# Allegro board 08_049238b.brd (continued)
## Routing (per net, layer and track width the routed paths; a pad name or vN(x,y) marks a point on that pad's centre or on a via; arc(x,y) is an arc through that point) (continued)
APLANE: length 1936.4
  TOP w0.203: U4.11 90.81,84.74 ; U4.23 89.29,89.65 v1(89.15,89.79)
  TOP w0.254: 5.01,94.99 P2.BG4 5.01,97.1 ; C31.2 86.23,94.11 ; 51.18,89.53 C13.2 49.4,89.53 ; 85.72,99.21 J3.5 ; J3.5 84.23,100.71 ; J3.5 87.22,100.71 ; J3.5 85.72,102.21 ; 101.6,142.46 P6.1 ; P6.1 99.91,144.14 ; P6.1 101.6,145.83 ; P6.1 103.29,144.14 ; 51.18,163.07 C5.2 49.4,163.07 ; TP10.1 81.06,156.97 ; TP10.1 77.94,156.97 ; TP10.1 79.5,155.41 ; TP10.1 79.5,158.53 ; J1.3 72.77,114.66 ; J1.3 72.77,111.66 ; J1.3 74.27,113.16 ; J1.3 71.27,113.16 ; 53.21,80.9 54.1,80.9 54.1,79.97 ; 45.97,88.14 C20.2 ; 5.01,89.99 P2.BG2 5.01,92.1 ; TP12.1 38.35,158.66 ; TP12.1 38.35,155.54 ; TP12.1 39.92,157.1 ; TP12.1 36.79,157.1 ; 31.37,163.19 C42.2 29.59,163.19 ; 54.23,15.98 XC1.2 55.26,17.06 ; 92.52,127.72 C113.2 ; 5.01,73.56 P1.BG5 5.01,71.45 ; P2.DG9 9.51,109.6 ; P2.DG9 9.51,107.49 ; P2.DG9 10.56,108.54 ; 29.38,8.44 XP2.PAD2 ; XP2.PAD2 30.87,6.71 ; XP2.PAD2 32.36,8.44 ; 89.31,100.71 J3.4 ; J3.4 90.81,102.21 ; J3.4 92.3,100.71 ; J3.4 90.81,99.21 ; v1(93.47,85.72) 93.21,85.99 U4.14 ; P1.DG9 10.56,82.51 ; P1.DG9 9.51,81.45 ; P1.DG9 9.51,83.56 ; P2.DG4 10.56,96.04 ; P2.DG4 9.51,97.1 ; P2.DG4 9.51,94.99 ; 5.01,61.45 P1.BG1 5.01,63.56 ; 5.01,102.1 P2.BG6 5.01,99.99 ; 5.01,99.6 P2.BG5 5.01,97.49 ; 101.15,84.65 J6.3 ; 70.51,132.44 S2.4 ; S2.4 72.75,132.44 ; S2.4 71.63,131.19 ; J2.5 36.3,70.99 ; J2.5 34.8,72.49 ; J2.5 34.8,69.49 ; J2.5 33.3,70.99 ; 79.12,58.83 J4.5 ; J4.5 80.62,60.33 ; J4.5 77.62,60.33 ; J4.5 79.12,61.82 ; 51.02,15.32 XC4.N 53.18,15.32 ; 106.02,135.38 C1.N 103.02,135.38 ; P1.DG5 10.56,72.51 ; P1.DG5 9.51,71.45 ; P1.DG5 9.51,73.56 ; 9.51,104.99 P2.DG8 ; P2.DG8 10.56,106.04 ; P2.DG8 9.51,107.1 ; C24.2 94.87,93.35 ; TP4.1 20.74,157.23 ; TP4.1 19.18,155.66 ; TP4.1 19.18,158.79 ; TP4.1 17.61,157.23 ; 14.73,139.86 C110.N ; 32.73,95.73 DS2.C 32.73,94 ; 5.01,68.95 P1.BG4 5.01,71.06 ; 86.3,142.46 P6.2 ; P6.2 84.61,144.14 ; P6.2 86.3,145.83 ; P6.2 87.99,144.14 ; P2.DG2 10.56,91.04 ; P2.DG2 9.51,89.99 ; P2.DG2 9.51,92.1 ; 79.12,63.91 J4.2 ; J4.2 80.62,65.41 ; J4.2 79.12,66.9 ; J4.2 77.62,65.41 ; 54.5,34.42 XU1.7 ; v1(93.34,87.88) 92.95,87.49 U4.17 ; 63.25,168.2 U6.1 64.3,169.65 ; 5.01,102.49 P2.BG7 5.01,104.6 ; TP19.1 96.52,135.55 ; TP19.1 94.96,133.99 ; TP19.1 98.08,133.99 ; 9.51,61.45 P1.DG1 ; P1.DG1 9.51,63.56 ; P1.DG1 10.56,62.51 ; 32.73,19.42 XC6.2 32.73,17.26 ; v3(87,85.85) 87.13,85.99 U4.5 ; 29.86,33.02 XU3.7 30.56,31.65 ; 44.49,169.77 U11.1 43.43,168.33 ; J1.2 69.19,113.16 ; J1.2 67.69,114.66 ; J1.2 67.69,111.66 ; J1.2 66.19,113.16 ; U4.2 87.26,87.49 v3(87.12,87.63) ; 29.72,167.58 C56.N 29.72,169.74 ; J2.2 34.8,77.57 ; J2.2 33.3,76.07 ; J2.2 36.3,76.07 ; J2.2 34.8,74.57 ; 83.19,84.96 C22.1 ; 5.01,83.95 P1.BG10 5.01,86.06 ; P2.DG3 10.56,93.54 ; P2.DG3 9.51,92.49 ; P2.DG3 9.51,94.6 ; C33.2 57.09,166.03 ; 5.01,76.45 P1.BG7 5.01,78.56 ; 9.51,109.99 P2.DG10 ; P2.DG10 9.51,112.1 ; P2.DG10 10.56,111.04 ; 30.87,1.26 XP2.PAD3 ; XP2.PAD3 30.87,4.72 ; XP2.PAD3 29.38,2.99 ; 9.51,76.45 P1.DG7 ; P1.DG7 9.51,78.56 ; P1.DG7 10.56,77.51 ; 39.88,69.49 J2.4 ; J2.4 38.38,70.99 ; J2.4 39.88,72.49 ; J2.4 41.38,70.99 ; 71.4,46.23 72.52,46.23 ; 72.52,46.23 72.52,47.47 ; 72.52,46.23 72.52,44.98 ; 5.01,92.49 P2.BG3 5.01,94.6 ; P1.DG3 9.51,68.56 ; P1.DG3 9.51,66.45 ; P1.DG3 10.56,67.51 ; P1.DG10 10.56,85.01 ; P1.DG10 9.51,86.06 ; P1.DG10 9.51,83.95 ; 9.51,97.49 P2.DG5 ; P2.DG5 10.56,98.54 ; P2.DG5 9.51,99.6 ; 71.78,59.18 S1.1 ; S1.1 74.27,59.18 ; S1.1 73.03,60.3 ; C11.2 52.45,86.36 ; 30.52,169.99 C62.2 30.52,172.15 ; P1.DG8 9.51,81.06 ; P1.DG8 10.56,80.01 ; P1.DG8 9.51,78.95 ; 60.62,57.02 R5.2 59.69,57.91 ; 5.01,112.1 P2.BG10 5.01,109.99 ; 9.51,68.95 P1.DG4 ; P1.DG4 9.51,71.06 ; P1.DG4 10.56,70.01 ; 50.8,83.19 49.02,83.19 ; P2.DG6 9.51,102.1 ; P2.DG6 9.51,99.99 ; P2.DG6 10.56,101.04 ; XC7.2 32.75,17.18 ; 32.6,100.05 DS1.C 32.6,98.32 ; 85.72,104.29 J3.2 ; J3.2 84.23,105.79 ; J3.2 87.22,105.79 ; J3.2 85.72,107.29 ; XU2.6 v1(36.32,17.53) ; J2.3 39.88,77.57 ; J2.3 41.38,76.07 ; J2.3 39.88,74.57 ; J2.3 38.38,76.07 ; P2.DG1 10.56,88.54 ; P2.DG1 9.51,87.49 ; P2.DG1 9.51,89.6 ; XY1.4 55.63,19.13 ; XY1.4 54.55,20.52 ; XY1.4 53.47,19.13 ; 50.46,172.02 C57.2 50.46,169.86 ; 101.15,89.34 J6.2 104.41,91.55 ; J4.4 84.2,61.82 ; J4.4 82.7,60.33 ; J4.4 84.2,58.83 ; J4.4 85.7,60.33 ; P1.DG2 9.51,66.06 ; P1.DG2 10.56,65.01 ; P1.DG2 9.51,63.95 ; 84.2,63.91 J4.3 ; J4.3 84.2,66.9 ; J4.3 82.7,65.41 ; J4.3 85.7,65.41 ; J1.4 72.77,109.58 ; J1.4 71.27,108.08 ; J1.4 74.27,108.08 ; J1.4 72.77,106.58 ; 5.01,89.6 P2.BG1 5.01,87.49 ; 10.67,169.86 C52.N 10.67,167.7 ; 59.69,115.54 R19.2 ; R4.2 59.69,119.48 ; P2.DG7 9.51,104.6 ; P2.DG7 10.56,103.54 ; P2.DG7 9.51,102.49 ; S1.2 65.15,60.3 ; S1.2 66.4,59.18 ; S1.2 63.91,59.18 ; 46.36,83.57 46.36,84.46 ; 46.36,83.57 47.28,83.57 ; 46.36,83.57 46.36,82.68 ; 37.28,166.15 C105.2 35.11,166.15 ; 92.27,128.65 C112.N 90.11,128.65 ; 59.69,53.95 R18.2 ; 72.52,54.1 72.52,55.35 ; 72.52,54.1 72.52,52.86 ; 72.52,54.1 71.4,54.1 ; 24.26,168.45 U7.1 25.31,169.9 ; 86.87,129.54 C115.2 86.87,127.76 ; J1.5 69.19,108.08 ; J1.5 67.69,109.58 ; J1.5 67.69,106.58 ; J1.5 66.19,108.08 ; TP2.1 59.73,156.97 ; TP2.1 58.17,155.41 ; TP2.1 58.17,158.53 ; TP2.1 56.6,156.97 ; 84.58,168.2 U10.1 85.64,169.65 ; 11.34,172.28 C58.2 11.34,170.12 ; P1.DG6 9.51,76.06 ; P1.DG6 9.51,73.95 ; P1.DG6 10.56,75.01 ; 5.01,107.49 P2.BG9 5.01,109.6 ; 91.29,83.76 U4.12 ; 49.4,94.49 C12.2 ; C12.2 50.29,95.42 ; C12.2 51.18,94.49 ; 70.99,169.61 C55.N 70.99,167.45 ; XU2.31 45.93,19.48 v1(46.23,19.18) 45.88,18.83 XU2.30 ; 5.01,68.56 P1.BG3 5.01,66.45 ; 56.22,24.73 XC2.2 ; J3.3 90.81,107.29 ; J3.3 90.81,104.29 ; J3.3 89.31,105.79 ; J3.3 92.3,105.79 ; 86.23,89.28 C40.2 ; 21.96,1.26 XP2.PAD4 ; XP2.PAD4 21.96,4.72 ; XP2.PAD4 23.45,2.99 ; 90.79,83.76 U4.11 ; 49.66,167.45 C51.N 49.66,169.61 ; 39.38,99.39 U15.4 40.02,100 v1(39.75,100.26) ; 5.01,83.56 P1.BG9 5.01,81.45 ; U4.19 91.29,89.56 v1(91.06,89.79) 90.79,89.52 U4.20 ; 52.2,83.31 52.2,84.2 ; 40.89,82.93 C21.2 40.89,81.15 ; C10.2 44.96,95.29 ; 32.73,96.16 CR3.C 32.73,97.89 ; C92.N 76.58,117.79 ; S2.3 71.63,125.81 ; S2.3 72.75,124.56 ; S2.3 70.51,124.56 ; 41.24,89.66 C7.2 ; XY1.2 56.95,24.52 ; XY1.2 55.87,23.13 ; XY1.2 56.95,21.75 ; 35.33,6.34 XP1.6 ; XP1.6 35.33,8.95 ; XP1.6 34.02,7.65 ; 72.52,163.07 C39.2 70.74,163.07 ; 72.17,169.73 C61.2 ; 5.01,78.95 P1.BG8 5.01,81.06 ; C37.2 78.42,166.03 ; 5.01,76.06 P1.BG6 5.01,73.95 ; 5.01,104.99 P2.BG8 5.01,107.1 ; 21.96,6.71 XP2.PAD1 ; XP2.PAD1 21.96,10.17 ; XP2.PAD1 23.45,8.44 ; XP2.5 28.85,8.55 ; C34.2 18.1,166.28 ; 5.01,66.06 P1.BG2 5.01,63.95 ; 12.32,163.32 C43.2 10.54,163.32 ; 94.74,88.26 C38.2 ; XC8.2 50.61,16.17
  TOP w0.279: U4.8 89.29,84.1 88.89,83.7 ; v1(91.06,83.82) 90.81,84.07 90.81,84.74
  TOP w0.381: XU3.7 v1(30.56,34.59) ; XU1.7 v1(55.2,35.81)
  TOP w0.508: v1(76.71,84.45) C99.1 ; C99.1 v1(75.18,84.45) ; C99.1 v1(75.95,85.47) ; v1(71.37,84.45) C75.1 ; C75.1 v1(72.14,85.47) ; C75.1 v1(72.77,84.45) ; XP2.PAD4 v3(20,2.99) ; U4.12 v3(91.92,84.74) ; C37.2 v1(77.34,165.23) ; C11.2 v3(51.44,85.47) ; v1(49.78,14.86) 49.53,15.11 XC8.2 ; XC3.2 v1(43.78,25.23) ; v1(104.01,83.82) 104.41,84.21 J6.3 ; XC1.2 v3(55.26,14.87) ; C56.N v1(28.32,168.66) ; C57.2 v1(49.53,170.94) ; v3(68.33,85.47) C74.1 ; C74.1 v3(67.44,84.45) ; C74.1 v3(69.22,84.45) ; v1(71.21,80.64) C64.2 ; C64.2 v1(72.14,79.63) ; C64.2 v1(73.03,80.64) ; 72.14,89.03 v1(71.37,89.03) ; 72.14,89.03 v1(72.14,88.01) ; 72.14,89.03 v1(72.9,89.03) ; C13.2 v3(50.29,88.65) ; XC6.2 v3(31.57,18.34) ; v1(67.92,80.57) 68,80.64 C65.2 ; S2.4 v3(71.63,133.71) ; C22.1 v1(82.55,85.85) ; v1(102.49,90.04) 103.12,90.04 J6.2 ; C33.2 v1(56.01,165.1) ; C30.2 v1(18.8,172.34) ; CR3.C 31.24,97.03 v1(31.37,97.16) ; C55.N v1(69.6,168.53) ; J6.2 105.03,89.69 v1(105.03,90.04) ; J6.2 104.41,89.4 v1(103.76,90.04) ; J6.2 106.93,90.04 v1(106.3,90.04) ; XC4.N v1(52.1,14.07) ; 68.33,89.03 v1(68.33,88.01) ; 68.33,89.03 v1(67.94,89.03) ; 68.33,89.03 v1(69.09,89.03) ; v1(75.95,88.01) 75.95,89.03 ; 75.95,89.03 v1(76.71,89.03) ; 75.95,89.03 v1(75.18,89.03) ; C65.2 v1(68.33,79.63) ; C65.2 v1(69.25,80.64) ; C52.N v1(9.27,168.78) ; v1(14.73,142.09) C110.N v1(16.26,140.94) ; XC5.2 47.42,14.94 v1(47.5,14.86) ; J6.3 106.93,83.82 v1(106.43,83.82) ; J6.3 103.12,83.82 v1(102.62,83.82) ; J6.3 105.28,84.12 v1(105.28,83.82) ; 72.14,92.84 v1(72.14,93.98) ; 72.14,92.84 v1(73.06,92.84) ; 72.14,92.84 v1(71.21,92.84) ; C61.2 v3(70.99,170.81) ; C49.1 v1(75.06,92.96) ; C49.1 v1(76.71,92.96) ; C49.1 v1(75.95,93.98) ; C113.2 v1(93.6,128.82) ; 72.52,46.23 v3(73.66,46.23) ; R5.2 59.69,57 v1(60.58,57) ; XC7.2 v3(31.47,16.1) ; XP2.5 v1(28.12,10.11) ; C43.2 v1(11.43,164.08) ; 52.2,84.2 51.82,83.82 v3(51.44,84.2) ; C39.2 v1(71.63,163.83) ; U7.1 v1(24.26,171.58) ; U11.1 v1(43.43,171.07) ; S1.1 v3(73.03,57.78) ; C34.2 v1(17.02,165.35) ; C42.2 v1(30.48,164.21) ; C51.N v1(48.39,168.53) ; C5.2 v1(50.29,163.83) ; v3(59.69,96.52) C147.N v3(59.69,99.19) ; 54.1,80.9 v1(54.74,80.9) ; R18.2 v3(60.81,54.84) ; XD1.C v1(51.59,25.3) ; C10.2 v1(44.2,94.36) ; XY1.2 v1(57.77,23.13) ; v1(31.5,99.19) DS1.C ; v1(76.58,115.06) C92.N v1(78.49,116.71) ; R4.2 v1(60.58,118.59) ; 68.33,92.84 v1(67.82,92.84) ; 68.33,92.84 v1(68.33,93.98) ; 68.33,92.84 v1(69.25,92.84) ; C62.2 v1(29.59,171.07) ; C101.2 v1(75.18,80.64) ; C101.2 v1(76.87,80.64) ; C101.2 v1(75.95,79.63) ; 88.89,83.7 88.84,83.65 v1(88.65,83.65) ; C112.N v1(91.19,129.92) ; R19.2 v1(60.45,116.43) ; XP2.PAD2 v1(30.87,10.23) ; C115.2 v1(87.5,128.65) ; C21.2 v3(40.01,82.04) ; C111.2 v1(37.97,172.21) ; U6.1 v1(63.25,171.07) ; C9.2 45.89,94.74 v3(45.88,94.73) ; S2.3 v3(71.63,123.67) ; C20.2 46.61,89.03 v3(48.83,86.8) ; XP2.PAD3 v3(32.7,2.99) ; U10.1 v1(84.58,171.32) ; C105.2 v1(36.2,165.35) ; XY1.4 v1(54.55,17.71) ; v3(49.91,83.95) 49.91,83.19 ; C7.2 v3(42.16,89.03) ; 46.36,83.57 v3(46.86,84.07) ; v1(104.52,136.91) C1.N v1(104.52,133.86) ; 72.52,54.1 v3(73.79,54.1) ; XP2.PAD1 v3(20.12,8.44) ; C27.2 v1(57.53,172.08) ; C12.2 49.28,95.5 v1(49.28,96.01) ; S1.2 v3(65.15,57.78) ; C58.2 v1(10.25,171.2) ; C63.2 v1(79.12,172.08) ; XC2.2 v3(57.56,25.81) ; v1(31.37,94.87) DS2.C
  TOP w0.635: C36.2 v1(85.22,91.57) ; C24.2 v1(95.76,92.46) ; C38.2 v1(95.63,89.15) ; C40.2 v1(85.34,90.17) ; C31.2 v1(85.47,93.22) ; C35.2 v1(95.76,90.68)
  L2_GND w0.381: P2.DG9 10.51,108.54 ; P2.DG9 9.51,107.54 ; P2.DG9 9.51,109.55 ; 5.01,73.51 P1.BG5 5.01,71.51 ; 79.12,63.96 J4.2 ; J4.2 77.67,65.41 ; J4.2 80.57,65.41 ; J4.2 79.12,66.85 ; P2.DG10 9.51,112.05 ; P2.DG10 9.51,110.04 ; P2.DG10 10.51,111.04 ; 5.01,87.54 P2.BG1 5.01,89.55 ; 5.01,61.51 P1.BG1 5.01,63.51 ; 9.51,90.04 P2.DG2 ; P2.DG2 10.51,91.04 ; P2.DG2 9.51,92.05 ; TP19.1 96.52,135.5 ; TP19.1 98.03,133.99 ; TP19.1 95.01,133.99 ; TP19.1 96.52,132.47 ; 5.01,76.01 P1.BG6 5.01,74.01 ; J3.4 90.81,102.16 ; J3.4 92.25,100.71 ; J3.4 89.36,100.71 ; J3.4 90.81,99.26 ; J4.5 79.12,61.77 ; J4.5 80.57,60.33 ; J4.5 79.12,58.88 ; J4.5 77.67,60.33 ; 5.01,95.04 P2.BG4 5.01,97.05 ; P1.DG8 9.51,81.01 ; P1.DG8 10.51,80.01 ; P1.DG8 9.51,79.01 ; 9.51,66.51 P1.DG3 ; P1.DG3 10.51,67.51 ; P1.DG3 9.51,68.51 ; P6.2 86.3,145.78 ; P6.2 84.66,144.14 ; P6.2 87.94,144.14 ; P6.2 86.3,142.51 ; XP1.6 36.59,7.65 ; XP1.6 35.33,8.9 ; XP1.6 35.33,6.39 ; XP1.6 34.07,7.65 ; TP2.1 59.68,156.97 ; TP2.1 56.65,156.97 ; TP2.1 58.17,155.46 ; TP2.1 58.17,158.48 ; J3.5 85.72,102.16 ; J3.5 84.28,100.71 ; J3.5 85.72,99.26 ; J3.5 87.17,100.71 ; J1.3 74.22,113.16 ; J1.3 71.32,113.16 ; J1.3 72.77,111.71 ; J1.3 72.77,114.61 ; 9.51,87.54 P2.DG1 ; P2.DG1 10.51,88.54 ; P2.DG1 9.51,89.55 ; 90.81,104.34 J3.3 ; J3.3 89.36,105.79 ; J3.3 92.25,105.79 ; J3.3 90.81,107.24 ; J4.3 85.65,65.41 ; J4.3 84.2,63.96 ; J4.3 84.2,66.85 ; J4.3 82.75,65.41 ; 9.51,102.54 P2.DG7 ; P2.DG7 10.51,103.54 ; P2.DG7 9.51,104.55 ; 33.35,70.99 J2.5 ; J2.5 34.8,72.44 ; J2.5 36.25,70.99 ; J2.5 34.8,69.54 ; TP4.1 20.69,157.23 ; TP4.1 17.67,157.23 ; TP4.1 19.18,155.71 ; TP4.1 19.18,158.74 ; P2.DG4 9.51,97.05 ; P2.DG4 9.51,95.04 ; P2.DG4 10.51,96.04 ; J1.2 67.69,114.61 ; J1.2 67.69,111.71 ; J1.2 69.14,113.16 ; J1.2 66.24,113.16 ; 33.35,76.07 J2.2 ; J2.2 34.8,74.62 ; J2.2 34.8,77.52 ; J2.2 36.25,76.07 ; 5.01,84.01 P1.BG10 5.01,86.01 ; 5.01,92.54 P2.BG3 5.01,94.55 ; 9.51,76.51 P1.DG7 ; P1.DG7 10.51,77.51 ; P1.DG7 9.51,78.51 ; P1.DG10 9.51,86.01 ; P1.DG10 9.51,84.01 ; P1.DG10 10.51,85.01 ; 9.51,92.54 P2.DG3 ; P2.DG3 9.51,94.55 ; P2.DG3 10.51,93.54 ; P2.DG6 10.51,101.04 ; P2.DG6 9.51,102.05 ; P2.DG6 9.51,100.04 ; J2.4 41.33,70.99 ; J2.4 38.43,70.99 ; J2.4 39.88,72.44 ; J2.4 39.88,69.54 ; 5.01,76.51 P1.BG7 5.01,78.51 ; 5.01,97.54 P2.BG5 5.01,99.55 ; J3.2 85.72,107.24 ; J3.2 85.72,104.34 ; J3.2 84.28,105.79 ; J3.2 87.17,105.79 ; P1.DG2 9.51,66.01 ; P1.DG2 10.51,65.01 ; P1.DG2 9.51,64.01 ; 5.01,107.54 P2.BG9 5.01,109.55 ; P2.DG5 9.51,99.55 ; P2.DG5 9.51,97.54 ; P2.DG5 10.51,98.54 ; J2.3 39.88,77.52 ; J2.3 39.88,74.62 ; J2.3 41.33,76.07 ; J2.3 38.43,76.07 ; 5.01,69.01 P1.BG4 5.01,71.01 ; J4.4 85.65,60.33 ; J4.4 84.2,61.77 ; J4.4 82.75,60.33 ; J4.4 84.2,58.88 ; 9.51,81.51 P1.DG9 ; P1.DG9 10.51,82.51 ; P1.DG9 9.51,83.51 ; 5.01,102.54 P2.BG7 5.01,104.55 ; 101.6,142.51 P6.1 ; P6.1 101.6,145.78 ; P6.1 103.24,144.14 ; P6.1 99.96,144.14 ; 38.35,155.59 TP12.1 ; TP12.1 36.84,157.1 ; TP12.1 39.87,157.1 ; TP12.1 38.35,158.61 ; 5.01,81.01 P1.BG8 5.01,79.01 ; P1.DG1 10.51,62.51 ; P1.DG1 9.51,61.51 ; P1.DG1 9.51,63.51 ; J1.4 72.77,109.53 ; J1.4 72.77,106.63 ; J1.4 74.22,108.08 ; J1.4 71.32,108.08 ; 77.99,156.97 TP10.1 ; TP10.1 81.01,156.97 ; TP10.1 79.5,155.46 ; TP10.1 79.5,158.48 ; 5.01,64.01 P1.BG2 5.01,66.01 ; P1.DG4 10.51,70.01 ; P1.DG4 9.51,69.01 ; P1.DG4 9.51,71.01 ; 9.51,71.51 P1.DG5 ; P1.DG5 9.51,73.51 ; P1.DG5 10.51,72.51 ; J1.5 69.14,108.08 ; J1.5 67.69,109.53 ; J1.5 67.69,106.63 ; J1.5 66.24,108.08 ; 5.01,68.51 P1.BG3 5.01,66.51 ; 9.51,74.01 P1.DG6 ; P1.DG6 9.51,76.01 ; P1.DG6 10.51,75.01 ; 5.01,112.05 P2.BG10 5.01,110.04 ; 9.51,105.04 P2.DG8 ; P2.DG8 9.51,107.05 ; P2.DG8 10.51,106.04 ; 5.01,105.04 P2.BG8 5.01,107.05 ; 5.01,102.05 P2.BG6 5.01,100.04 ; 5.01,83.51 P1.BG9 5.01,81.51 ; 5.01,90.04 P2.BG2 5.01,92.05
  L4_GND w0.254: J2.3 41.33,76.07 ; J2.3 39.88,77.52 ; J2.3 39.88,74.62 ; J2.3 38.43,76.07 ; 5.01,97.05 P2.BG4 5.01,95.04 ; J4.2 80.57,65.41 ; J4.2 79.12,66.85 ; J4.2 79.12,63.96 ; J4.2 77.67,65.41 ; 5.01,69.01 P1.BG4 5.01,71.01 ; 66.24,113.16 J1.2 ; J1.2 69.14,113.16 ; J1.2 67.69,111.71 ; J1.2 67.69,114.61 ; P1.DG2 9.51,66.01 ; P1.DG2 10.51,65.01 ; P1.DG2 9.51,64.01 ; 9.51,79.01 P1.DG8 ; P1.DG8 9.51,81.01 ; P1.DG8 10.51,80.01 ; 9.51,97.54 P2.DG5 ; P2.DG5 10.51,98.54 ; P2.DG5 9.51,99.55 ; 9.51,76.51 P1.DG7 ; P1.DG7 9.51,78.51 ; P1.DG7 10.51,77.51 ; 72.77,106.63 J1.4 ; J1.4 71.32,108.08 ; J1.4 72.77,109.53 ; J1.4 74.22,108.08 ; 9.51,102.54 P2.DG7 ; P2.DG7 9.51,104.55 ; P2.DG7 10.51,103.54 ; P1.DG9 10.51,82.51 ; P1.DG9 9.51,83.51 ; P1.DG9 9.51,81.51 ; P1.DG3 9.51,68.51 ; P1.DG3 9.51,66.51 ; P1.DG3 10.51,67.51 ; P6.1 103.24,144.14 ; P6.1 99.96,144.14 ; P6.1 101.6,145.78 ; P6.1 101.6,142.51 ; 86.3,142.51 P6.2 ; P6.2 86.3,145.78 ; P6.2 87.94,144.14 ; P6.2 84.66,144.14 ; P2.DG9 9.51,109.55 ; P2.DG9 10.51,108.54 ; P2.DG9 9.51,107.54 ; 77.67,60.33 J4.5 ; J4.5 80.57,60.33 ; J4.5 79.12,58.88 ; J4.5 79.12,61.77 ; P2.DG6 10.51,101.04 ; P2.DG6 9.51,102.05 ; P2.DG6 9.51,100.04 ; J4.4 84.2,61.77 ; J4.4 85.65,60.33 ; J4.4 82.75,60.33 ; J4.4 84.2,58.88 ; 5.01,99.55 P2.BG5 5.01,97.54 ; J3.5 85.72,102.16 ; J3.5 84.28,100.71 ; J3.5 85.72,99.26 ; J3.5 87.17,100.71 ; 34.07,7.65 XP1.6 ; XP1.6 35.33,8.9 ; XP1.6 35.33,6.39 ; XP1.6 36.59,7.65 ; 56.65,156.97 TP2.1 ; TP2.1 58.17,155.46 ; TP2.1 59.68,156.97 ; TP2.1 58.17,158.48 ; 9.51,90.04 P2.DG2 ; P2.DG2 9.51,92.05 ; P2.DG2 10.51,91.04 ; 5.01,61.51 P1.BG1 5.01,63.51 ; J4.3 85.65,65.41 ; J4.3 84.2,66.85 ; J4.3 82.75,65.41 ; J4.3 84.2,63.96 ; J2.5 36.25,70.99 ; J2.5 34.8,69.54 ; J2.5 34.8,72.44 ; J2.5 33.35,70.99 ; 95.01,133.99 TP19.1 ; TP19.1 96.52,135.5 ; TP19.1 98.03,133.99 ; TP19.1 96.52,132.47 ; 85.72,104.34 J3.2 ; J3.2 84.28,105.79 ; J3.2 87.17,105.79 ; J3.2 85.72,107.24 ; 5.01,90.04 P2.BG2 5.01,92.05 ; 72.77,111.71 J1.3 ; J1.3 74.22,113.16 ; J1.3 71.32,113.16 ; J1.3 72.77,114.61 ; 5.01,107.54 P2.BG9 5.01,109.55 ; 90.81,104.34 J3.3 ; J3.3 89.36,105.79 ; J3.3 92.25,105.79 ; J3.3 90.81,107.24 ; 5.01,102.05 P2.BG6 5.01,100.04 ; P1.DG1 10.51,62.51 ; P1.DG1 9.51,61.51 ; P1.DG1 9.51,63.51 ; P1.DG5 10.51,72.51 ; P1.DG5 9.51,71.51 ; P1.DG5 9.51,73.51 ; 5.01,107.05 P2.BG8 5.01,105.04 ; P2.DG8 9.51,107.05 ; P2.DG8 10.51,106.04 ; P2.DG8 9.51,105.04 ; 5.01,104.55 P2.BG7 5.01,102.54 ; TP12.1 38.35,158.61 ; TP12.1 39.87,157.1 ; TP12.1 36.84,157.1 ; TP12.1 38.35,155.59 ; P2.DG1 9.51,89.55 ; P2.DG1 9.51,87.54 ; P2.DG1 10.51,88.54 ; 66.24,108.08 J1.5 ; J1.5 69.14,108.08 ; J1.5 67.69,109.53 ; J1.5 67.69,106.63 ; 5.01,76.01 P1.BG6 5.01,74.01 ; TP10.1 79.5,158.48 ; TP10.1 81.01,156.97 ; TP10.1 79.5,155.46 ; TP10.1 77.99,156.97 ; 5.01,92.54 P2.BG3 5.01,94.55 ; J2.2 34.8,77.52 ; J2.2 33.35,76.07 ; J2.2 36.25,76.07 ; J2.2 34.8,74.62 ; 5.01,78.51 P1.BG7 5.01,76.51 ; P1.DG10 10.51,85.01 ; P1.DG10 9.51,84.01 ; P1.DG10 9.51,86.01 ; J3.4 92.25,100.71 ; J3.4 90.81,102.16 ; J3.4 90.81,99.26 ; J3.4 89.36,100.71 ; P2.DG4 9.51,97.05 ; P2.DG4 9.51,95.04 ; P2.DG4 10.51,96.04 ; P2.DG10 10.51,111.04 ; P2.DG10 9.51,112.05 ; P2.DG10 9.51,110.04 ; P1.DG6 9.51,76.01 ; P1.DG6 10.51,75.01 ; P1.DG6 9.51,74.01 ; P2.DG3 10.51,93.54 ; P2.DG3 9.51,94.55 ; P2.DG3 9.51,92.54 ; 5.01,79.01 P1.BG8 5.01,81.01 ; P1.DG4 10.51,70.01 ; P1.DG4 9.51,69.01 ; P1.DG4 9.51,71.01 ; 5.01,64.01 P1.BG2 5.01,66.01 ; 5.01,68.51 P1.BG3 5.01,66.51 ; TP4.1 20.69,157.23 ; TP4.1 19.18,155.71 ; TP4.1 19.18,158.74 ; TP4.1 17.67,157.23 ; 5.01,81.51 P1.BG9 5.01,83.51 ; 5.01,110.04 P2.BG10 5.01,112.05 ; J2.4 39.88,72.44 ; J2.4 38.43,70.99 ; J2.4 41.33,70.99 ; J2.4 39.88,69.54 ; 5.01,73.51 P1.BG5 5.01,71.51 ; 5.01,87.54 P2.BG1 5.01,89.55 ; 5.01,86.01 P1.BG10 5.01,84.01
  L7_GND w0.254: P6.1 101.6,145.78 ; P6.1 103.24,144.14 ; P6.1 99.96,144.14 ; P6.1 101.6,142.51 ; 5.01,68.51 P1.BG3 5.01,66.51 ; 5.01,112.05 P2.BG10 5.01,110.04 ; J3.4 90.81,102.16 ; J3.4 92.25,100.71 ; J3.4 89.36,100.71 ; J3.4 90.81,99.26 ; 5.01,97.54 P2.BG5 5.01,99.55 ; 84.2,63.96 J4.3 ; J4.3 85.65,65.41 ; J4.3 84.2,66.85 ; J4.3 82.75,65.41 ; 5.01,74.01 P1.BG6 5.01,76.01 ; 9.51,87.54 P2.DG1 ; P2.DG1 10.51,88.54 ; P2.DG1 9.51,89.55 ; P2.DG8 10.51,106.04 ; P2.DG8 9.51,107.05 ; P2.DG8 9.51,105.04 ; TP4.1 20.69,157.23 ; TP4.1 17.67,157.23 ; TP4.1 19.18,155.71 ; TP4.1 19.18,158.74 ; TP12.1 39.87,157.1 ; TP12.1 38.35,158.61 ; TP12.1 38.35,155.59 ; TP12.1 36.84,157.1 ; 66.24,108.08 J1.5 ; J1.5 67.69,106.63 ; J1.5 67.69,109.53 ; J1.5 69.14,108.08 ; XP1.6 36.59,7.65 ; XP1.6 34.07,7.65 ; XP1.6 35.33,6.39 ; XP1.6 35.33,8.9 ; 72.77,106.63 J1.4 ; J1.4 74.22,108.08 ; J1.4 72.77,109.53 ; J1.4 71.32,108.08 ; 84.2,58.88 J4.4 ; J4.4 85.65,60.33 ; J4.4 84.2,61.77 ; J4.4 82.75,60.33 ; P1.DG2 9.51,66.01 ; P1.DG2 10.51,65.01 ; P1.DG2 9.51,64.01 ; 79.12,63.96 J4.2 ; J4.2 79.12,66.85 ; J4.2 80.57,65.41 ; J4.2 77.67,65.41 ; P1.DG4 10.51,70.01 ; P1.DG4 9.51,69.01 ; P1.DG4 9.51,71.01 ; J4.5 79.12,61.77 ; J4.5 77.67,60.33 ; J4.5 79.12,58.88 ; J4.5 80.57,60.33 ; J2.5 36.25,70.99 ; J2.5 34.8,72.44 ; J2.5 33.35,70.99 ; J2.5 34.8,69.54 ; 86.3,142.51 P6.2 ; P6.2 86.3,145.78 ; P6.2 87.94,144.14 ; P6.2 84.66,144.14 ; P1.DG10 9.51,86.01 ; P1.DG10 9.51,84.01 ; P1.DG10 10.51,85.01 ; 66.24,113.16 J1.2 ; J1.2 67.69,111.71 ; J1.2 69.14,113.16 ; J1.2 67.69,114.61 ; 9.51,92.54 P2.DG3 ; P2.DG3 9.51,94.55 ; P2.DG3 10.51,93.54 ; 5.01,83.51 P1.BG9 5.01,81.51 ; 5.01,76.51 P1.BG7 5.01,78.51 ; TP2.1 59.68,156.97 ; TP2.1 58.17,155.46 ; TP2.1 56.65,156.97 ; TP2.1 58.17,158.48 ; 9.51,97.54 P2.DG5 ; P2.DG5 10.51,98.54 ; P2.DG5 9.51,99.55 ; P1.DG9 9.51,83.51 ; P1.DG9 10.51,82.51 ; P1.DG9 9.51,81.51 ; 90.81,104.34 J3.3 ; J3.3 89.36,105.79 ; J3.3 90.81,107.24 ; J3.3 92.25,105.79 ; J2.2 34.8,77.52 ; J2.2 34.8,74.62 ; J2.2 36.25,76.07 ; J2.2 33.35,76.07 ; P2.DG2 9.51,92.05 ; P2.DG2 9.51,90.04 ; P2.DG2 10.51,91.04 ; 5.01,71.01 P1.BG4 5.01,69.01 ; P2.DG4 10.51,96.04 ; P2.DG4 9.51,97.05 ; P2.DG4 9.51,95.04 ; 5.01,94.55 P2.BG3 5.01,92.54 ; 5.01,105.04 P2.BG8 5.01,107.05 ; P1.DG6 9.51,76.01 ; P1.DG6 9.51,74.01 ; P1.DG6 10.51,75.01 ; P1.DG5 9.51,73.51 ; P1.DG5 10.51,72.51 ; P1.DG5 9.51,71.51 ; 84.28,100.71 J3.5 ; J3.5 85.72,102.16 ; J3.5 87.17,100.71 ; J3.5 85.72,99.26 ; J1.3 72.77,114.61 ; J1.3 71.32,113.16 ; J1.3 74.22,113.16 ; J1.3 72.77,111.71 ; TP19.1 96.52,135.5 ; TP19.1 95.01,133.99 ; TP19.1 98.03,133.99 ; TP19.1 96.52,132.47 ; P2.DG10 10.51,111.04 ; P2.DG10 9.51,112.05 ; P2.DG10 9.51,110.04 ; 9.51,66.51 P1.DG3 ; P1.DG3 10.51,67.51 ; P1.DG3 9.51,68.51 ; TP10.1 81.01,156.97 ; TP10.1 77.99,156.97 ; TP10.1 79.5,155.46 ; TP10.1 79.5,158.48 ; 5.01,89.55 P2.BG1 5.01,87.54 ; P2.DG9 10.51,108.54 ; P2.DG9 9.51,107.54 ; P2.DG9 9.51,109.55 ; P2.DG7 9.51,104.55 ; P2.DG7 9.51,102.54 ; P2.DG7 10.51,103.54 ; 5.01,100.04 P2.BG6 5.01,102.05 ; P1.DG1 10.51,62.51 ; P1.DG1 9.51,63.51 ; P1.DG1 9.51,61.51 ; 38.43,76.07 J2.3 ; J2.3 39.88,74.62 ; J2.3 41.33,76.07 ; J2.3 39.88,77.52 ; J2.4 41.33,70.99 ; J2.4 39.88,69.54 ; J2.4 39.88,72.44 ; J2.4 38.43,70.99 ; 5.01,109.55 P2.BG9 5.01,107.54 ; 5.01,64.01 P1.BG2 5.01,66.01 ; 5.01,95.04 P2.BG4 5.01,97.05 ; 5.01,71.51 P1.BG5 5.01,73.51 ; 5.01,81.01 P1.BG8 5.01,79.01 ; P1.DG7 9.51,78.51 ; P1.DG7 10.51,77.51 ; P1.DG7 9.51,76.51 ; 5.01,92.05 P2.BG2 5.01,90.04 ; J3.2 87.17,105.79 ; J3.2 84.28,105.79 ; J3.2 85.72,104.34 ; J3.2 85.72,107.24 ; 9.51,79.01 P1.DG8 ; P1.DG8 10.51,80.01 ; P1.DG8 9.51,81.01 ; 5.01,84.01 P1.BG10 5.01,86.01 ; P2.DG6 9.51,102.05 ; P2.DG6 9.51,100.04 ; P2.DG6 10.51,101.04 ; 5.01,61.51 P1.BG1 5.01,63.51 ; 5.01,102.54 P2.BG7 5.01,104.55
  L9_GND w0.254: 9.51,61.51 P1.DG1 ; P1.DG1 10.51,62.51 ; P1.DG1 9.51,63.51 ; P1.DG6 9.51,76.01 ; P1.DG6 9.51,74.01 ; P1.DG6 10.51,75.01 ; 5.01,99.55 P2.BG5 5.01,97.54 ; 9.51,110.04 P2.DG10 ; P2.DG10 9.51,112.05 ; P2.DG10 10.51,111.04 ; TP19.1 98.03,133.99 ; TP19.1 95.01,133.99 ; TP19.1 96.52,132.47 ; TP19.1 96.52,135.5 ; 5.01,100.04 P2.BG6 5.01,102.05 ; 9.51,66.51 P1.DG3 ; P1.DG3 10.51,67.51 ; P1.DG3 9.51,68.51 ; P1.DG10 10.51,85.01 ; P1.DG10 9.51,86.01 ; P1.DG10 9.51,84.01 ; 9.51,81.51 P1.DG9 ; P1.DG9 10.51,82.51 ; P1.DG9 9.51,83.51 ; P6.2 87.94,144.14 ; P6.2 86.3,145.78 ; P6.2 84.66,144.14 ; P6.2 86.3,142.51 ; 5.01,71.01 P1.BG4 5.01,69.01 ; P1.DG4 10.51,70.01 ; P1.DG4 9.51,71.01 ; P1.DG4 9.51,69.01 ; J2.5 34.8,72.44 ; J2.5 36.25,70.99 ; J2.5 33.35,70.99 ; J2.5 34.8,69.54 ; 9.51,100.04 P2.DG6 ; P2.DG6 9.51,102.05 ; P2.DG6 10.51,101.04 ; 36.84,157.1 TP12.1 ; TP12.1 39.87,157.1 ; TP12.1 38.35,158.61 ; TP12.1 38.35,155.59 ; 84.28,105.79 J3.2 ; J3.2 87.17,105.79 ; J3.2 85.72,104.34 ; J3.2 85.72,107.24 ; 9.51,87.54 P2.DG1 ; P2.DG1 10.51,88.54 ; P2.DG1 9.51,89.55 ; 9.51,64.01 P1.DG2 ; P1.DG2 9.51,66.01 ; P1.DG2 10.51,65.01 ; J2.3 39.88,77.52 ; J2.3 41.33,76.07 ; J2.3 39.88,74.62 ; J2.3 38.43,76.07 ; 66.24,108.08 J1.5 ; J1.5 67.69,109.53 ; J1.5 67.69,106.63 ; J1.5 69.14,108.08 ; 5.01,107.54 P2.BG9 5.01,109.55 ; P2.DG7 10.51,103.54 ; P2.DG7 9.51,102.54 ; P2.DG7 9.51,104.55 ; P6.1 101.6,145.78 ; P6.1 103.24,144.14 ; P6.1 101.6,142.51 ; P6.1 99.96,144.14 ; TP2.1 59.68,156.97 ; TP2.1 56.65,156.97 ; TP2.1 58.17,155.46 ; TP2.1 58.17,158.48 ; P1.DG8 9.51,81.01 ; P1.DG8 9.51,79.01 ; P1.DG8 10.51,80.01 ; J2.2 34.8,77.52 ; J2.2 36.25,76.07 ; J2.2 34.8,74.62 ; J2.2 33.35,76.07 ; J4.4 85.65,60.33 ; J4.4 82.75,60.33 ; J4.4 84.2,58.88 ; J4.4 84.2,61.77 ; 5.01,74.01 P1.BG6 5.01,76.01 ; 77.67,65.41 J4.2 ; J4.2 79.12,63.96 ; J4.2 79.12,66.85 ; J4.2 80.57,65.41 ; XP1.6 36.59,7.65 ; XP1.6 34.07,7.65 ; XP1.6 35.33,8.9 ; XP1.6 35.33,6.39 ; 5.01,64.01 P1.BG2 5.01,66.01 ; J1.4 72.77,109.53 ; J1.4 71.32,108.08 ; J1.4 72.77,106.63 ; J1.4 74.22,108.08 ; 5.01,92.54 P2.BG3 5.01,94.55 ; J2.4 41.33,70.99 ; J2.4 38.43,70.99 ; J2.4 39.88,69.54 ; J2.4 39.88,72.44 ; J1.3 74.22,113.16 ; J1.3 72.77,111.71 ; J1.3 71.32,113.16 ; J1.3 72.77,114.61 ; P2.DG4 10.51,96.04 ; P2.DG4 9.51,95.04 ; P2.DG4 9.51,97.05 ; 66.24,113.16 J1.2 ; J1.2 69.14,113.16 ; J1.2 67.69,111.71 ; J1.2 67.69,114.61 ; J4.3 84.2,66.85 ; J4.3 84.2,63.96 ; J4.3 85.65,65.41 ; J4.3 82.75,65.41 ; 5.01,81.01 P1.BG8 5.01,79.01 ; J4.5 80.57,60.33 ; J4.5 79.12,61.77 ; J4.5 77.67,60.33 ; J4.5 79.12,58.88 ; 9.51,105.04 P2.DG8 ; P2.DG8 9.51,107.05 ; P2.DG8 10.51,106.04 ; 5.01,63.51 P1.BG1 5.01,61.51 ; 5.01,76.51 P1.BG7 5.01,78.51 ; 5.01,66.51 P1.BG3 5.01,68.51 ; TP4.1 19.18,158.74 ; TP4.1 19.18,155.71 ; TP4.1 20.69,157.23 ; TP4.1 17.67,157.23 ; 9.51,71.51 P1.DG5 ; P1.DG5 10.51,72.51 ; P1.DG5 9.51,73.51 ; 5.01,89.55 P2.BG1 5.01,87.54 ; P2.DG5 9.51,99.55 ; P2.DG5 9.51,97.54 ; P2.DG5 10.51,98.54 ; P2.DG2 10.51,91.04 ; P2.DG2 9.51,90.04 ; P2.DG2 9.51,92.05 ; 5.01,81.51 P1.BG9 5.01,83.51 ; 9.51,92.54 P2.DG3 ; P2.DG3 10.51,93.54 ; P2.DG3 9.51,94.55 ; 9.51,107.54 P2.DG9 ; P2.DG9 9.51,109.55 ; P2.DG9 10.51,108.54 ; 5.01,110.04 P2.BG10 5.01,112.05 ; 89.36,100.71 J3.4 ; J3.4 90.81,102.16 ; J3.4 92.25,100.71 ; J3.4 90.81,99.26 ; 5.01,86.01 P1.BG10 5.01,84.01 ; J3.3 90.81,107.24 ; J3.3 89.36,105.79 ; J3.3 92.25,105.79 ; J3.3 90.81,104.34 ; TP10.1 79.5,158.48 ; TP10.1 77.99,156.97 ; TP10.1 79.5,155.46 ; TP10.1 81.01,156.97 ; J3.5 85.72,102.16 ; J3.5 84.28,100.71 ; J3.5 85.72,99.26 ; J3.5 87.17,100.71 ; 5.01,97.05 P2.BG4 5.01,95.04 ; 5.01,105.04 P2.BG8 5.01,107.05 ; 5.01,90.04 P2.BG2 5.01,92.05 ; 9.51,76.51 P1.DG7 ; P1.DG7 10.51,77.51 ; P1.DG7 9.51,78.51 ; 5.01,102.54 P2.BG7 5.01,104.55 ; 5.01,71.51 P1.BG5 5.01,73.51
  BOTTOM w0.254: 77.62,60.33 J4.5 ; J4.5 79.12,58.83 ; J4.5 80.62,60.33 ; J4.5 79.12,61.82 ; 10.56,62.51 P1.DG1 9.51,63.56 ; C67.2 20.41,85.28 ; 60.05,106.17 C91.2 59.02,105.09 ; TP19.1 98.08,133.99 ; TP19.1 96.52,132.42 ; TP19.1 96.52,135.55 ; TP19.1 94.96,133.99 ; 35.33,6.34 XP1.6 ; XP1.6 34.02,7.65 ; XP1.6 35.33,8.95 ; P1.DG10 9.51,86.06 ; P1.DG10 9.51,83.95 ; P1.DG10 10.56,85.01 ; 49.78,118.47 C72.2 50.67,117.54 ; 16.84,85.51 U3.13 16.24,86.12 v3(15.49,86.87) ; P6.2 86.3,145.83 ; P6.2 84.61,144.14 ; P6.2 87.99,144.14 ; P6.2 86.3,142.46 ; TP2.1 59.73,156.97 ; TP2.1 58.17,158.53 ; TP2.1 56.6,156.97 ; TP2.1 58.17,155.41 ; 85.72,104.29 J3.2 ; J3.2 85.72,107.29 ; J3.2 87.22,105.79 ; J3.2 84.23,105.79 ; 5.01,102.49 P2.BG7 5.01,104.6 ; 46.61,114.57 C150.2 45.72,113.64 ; P2.DG4 9.51,97.1 ; P2.DG4 9.51,94.99 ; P2.DG4 10.56,96.04 ; P1.DG5 9.51,73.56 ; P1.DG5 9.51,71.45 ; P1.DG5 10.56,72.51 ; 46.39,121.26 C122.2 45.47,122.15 ; TP10.1 79.5,158.53 ; TP10.1 77.94,156.97 ; TP10.1 81.06,156.97 ; TP10.1 79.5,155.41 ; 9.51,78.95 P1.DG8 ; P1.DG8 10.56,80.01 ; P1.DG8 9.51,81.06 ; 54.23,39.82 C114.N 52.73,38.73 ; J2.4 39.88,72.49 ; J2.4 39.88,69.49 ; J2.4 38.38,70.99 ; J2.4 41.38,70.99 ; 101.15,76.39 J15.3 104.41,78.6 ; P1.DG6 9.51,76.06 ; P1.DG6 10.56,75.01 ; P1.DG6 9.51,73.95 ; 5.01,109.6 P2.BG9 5.01,107.49 ; 9.51,66.45 P1.DG3 ; P1.DG3 10.56,67.51 ; P1.DG3 9.51,68.56 ; 44.45,51.92 C86.2 45.38,51.03 ; 5.01,81.45 P1.BG9 5.01,83.56 ; 54.23,42.71 C116.N 54.23,40.55 ; 57.7,59.16 C78.2 56.77,60.05 ; 51.44,55.35 C50.2 50.51,54.46 ; 5.01,73.56 P1.BG5 5.01,71.45 ; 67.69,106.58 J1.5 ; J1.5 69.19,108.08 ; J1.5 66.19,108.08 ; J1.5 67.69,109.58 ; P6.1 101.6,145.83 ; P6.1 103.29,144.14 ; P6.1 99.91,144.14 ; P6.1 101.6,142.46 ; P1.DG7 10.56,77.51 ; P1.DG7 9.51,78.56 ; P1.DG7 9.51,76.45 ; J3.4 92.3,100.71 ; J3.4 90.81,99.21 ; J3.4 89.31,100.71 ; J3.4 90.81,102.21 ; 5.01,109.99 P2.BG10 5.01,112.1 ; C87.2 57.82,117.07 ; 5.01,92.1 P2.BG2 5.01,89.99 ; J1.3 72.77,114.66 ; J1.3 72.77,111.66 ; J1.3 74.27,113.16 ; J1.3 71.27,113.16 ; 5.01,97.49 P2.BG5 5.01,99.6 ; 47.12,117.54 C77.2 ; 36.07,79.88 R9.2 36.07,78.1 ; T2.4 57.85,102.21 ; T2.4 56.67,101.35 ; T2.4 57.85,100.48 ; 77.62,65.41 J4.2 ; J4.2 80.62,65.41 ; J4.2 79.12,66.9 ; J4.2 79.12,63.91 ; P2.DG2 9.51,92.1 ; P2.DG2 10.56,91.04 ; P2.DG2 9.51,89.99 ; 33.3,76.07 J2.2 ; J2.2 36.3,76.07 ; J2.2 34.8,77.57 ; J2.2 34.8,74.57 ; 5.01,68.56 P1.BG3 5.01,66.45 ; 46.39,59.66 C69.2 45.47,60.55 ; 85.72,99.21 J3.5 ; J3.5 84.23,100.71 ; J3.5 85.72,102.21 ; J3.5 87.22,100.71 ; P1.DG9 9.51,83.56 ; P1.DG9 9.51,81.45 ; P1.DG9 10.56,82.51 ; 49.15,52.04 49.15,52.97 ; P1.BG1 5.01,63.56 ; C153.2 48.01,114.57 ; 58.55,64.03 R3.2 57.37,62.9 ; J4.3 85.7,65.41 ; J4.3 84.2,63.91 ; J4.3 84.2,66.9 ; J4.3 82.7,65.41 ; 5.01,83.95 P1.BG10 5.01,86.06 ; 57.37,124.5 R21.2 58.55,125.63 ; J2.3 39.88,77.57 ; J2.3 38.38,76.07 ; J2.3 41.38,76.07 ; J2.3 39.88,74.57 ; C200.2 50.29,52.97 ; 9.51,92.49 P2.DG3 ; P2.DG3 10.56,93.54 ; P2.DG3 9.51,94.6 ; 9.51,104.99 P2.DG8 ; P2.DG8 9.51,107.1 ; P2.DG8 10.56,106.04 ; J2.5 34.8,72.49 ; J2.5 34.8,69.49 ; J2.5 33.3,70.99 ; J2.5 36.3,70.99 ; 84.2,58.83 J4.4 ; J4.4 85.7,60.33 ; J4.4 84.2,61.82 ; J4.4 82.7,60.33 ; P1.DG2 9.51,66.06 ; P1.DG2 9.51,63.95 ; P1.DG2 10.56,65.01 ; 39.75,82.3 R32.2 ; 48.26,55.94 C46.2 49.15,56.87 ; TP4.1 19.18,158.79 ; TP4.1 20.74,157.23 ; TP4.1 17.61,157.23 ; TP4.1 19.18,155.66 ; 5.01,102.1 P2.BG6 5.01,99.99 ; 10.56,111.04 P2.DG10 9.51,112.1 ; 46.61,52.97 C68.2 45.72,52.04 ; P2.DG1 10.56,88.54 ; P2.DG1 9.51,87.49 ; P2.DG1 9.51,89.6 ; 53.21,55.94 C60.2 ; 45.38,112.62 C106.2 44.45,113.51 ; J1.4 72.77,109.58 ; J1.4 72.77,106.58 ; J1.4 74.27,108.08 ; J1.4 71.27,108.08 ; 5.01,94.99 P2.BG4 5.01,97.1 ; R27.2 59.73,83.31 ; 5.01,71.06 P1.BG4 5.01,68.95 ; 5.01,104.99 P2.BG8 5.01,107.1 ; 45.47,49 C54.2 45.47,50.78 ; C145.2 50.29,114.57 ; P2.DG6 10.56,101.04 ; P2.DG6 9.51,102.1 ; P2.DG6 9.51,99.99 ; C128.2 57.82,56.74 ; U1.37 50.65,81.69 50.67,81.66 50.67,80.52 v1(50.55,80.39) ; 90.81,104.29 J3.3 ; J3.3 90.81,107.29 ; J3.3 89.31,105.79 ; J3.3 92.3,105.79 ; C126.2 57.57,51.28 ; 50.51,53.31 C53.2 ; 51.27,121.26 52.2,121.26 ; 36.79,157.1 TP12.1 ; TP12.1 38.35,155.54 ; TP12.1 38.35,158.66 ; TP12.1 39.92,157.1 ; 20.41,80.96 C70.2 ; P1.DG4 10.56,70.01 ; P1.DG4 9.51,68.95 ; P1.DG4 9.51,71.06 ; 9.51,102.49 P2.DG7 ; P2.DG7 9.51,104.6 ; P2.DG7 10.56,103.54 ; P2.DG5 9.51,99.6 ; P2.DG5 10.56,98.54 ; P2.DG5 9.51,97.49 ; C25.2 19.27,93.28 ; 59.02,42.96 C118.2 59.02,45.12 ; 5.01,81.06 P1.BG8 5.01,78.95 ; 50.51,114.91 C154.2 ; 5.01,63.95 P1.BG2 5.01,66.06 ; 51.44,116.94 C148.2 50.51,116.05 ; 50.67,55.94 C202.2 49.78,56.87 ; U1.44 v1(47.14,81.28) ; 101.15,71.69 J15.2 104.41,69.48 ; 5.01,92.49 P2.BG3 5.01,94.6 ; 49.15,118.47 C149.2 48.26,117.54 ; 39.75,85.6 R23.2 ; U1.59 v3(45.19,87.99) ; 5.01,76.06 P1.BG6 5.01,73.95 ; J1.2 69.19,113.16 ; J1.2 67.69,111.66 ; J1.2 66.19,113.16 ; J1.2 67.69,114.66 ; C89.2 57.82,118.34 ; C120.2 57.57,50.14 ; 45.47,110.59 C117.2 45.47,112.37 ; 9.51,107.49 P2.DG9 10.56,108.54 ; C142.2 57.7,119.61 ; 47.12,55.94 C83.2 ; 5.01,89.6 P2.BG1 5.01,87.49 ; C84.2 57.7,58.01 ; R33.2 39.75,85.22 ; R28.2 59.73,84.45 ; C127.2 57.82,55.47 ; 5.01,78.56 P1.BG7 5.01,76.45 ; R42.2 59.73,87.63 ; C90.2 57.57,112.88 ; 51.27,59.66 52.2,59.66 ; 38.39,87.95 R11.1 ; R7.2 59.73,86.49 ; C85.2 57.57,111.73 ; 49.15,113.64 49.15,114.57 ; 53.21,117.54 C137.2 ; C140.2 56.77,121.64 ; 19.27,89.09 C66.2 ; C73.2 48.01,52.97
  BOTTOM w0.508: C91.2 v1(59.02,106.62) ; R33.2 v3(38.86,84.33) ; C77.2 46.74,118.47 v3(46.61,118.34) ; C67.2 v1(21.46,84.2) ; C85.2 57.25,111.12 v1(57.66,111.12) ; v1(46.67,97.73) 46.93,97.98 C26.2 ; v3(48.13,56.74) C46.2 ; v3(78.61,100.71) T7.5 v3(74.93,100.71) ; C86.2 v3(45.09,51.66) ; v3(58.67,82.42) 58.8,82.55 R27.2 ; v2(51.44,121.79) 51.56,121.67 51.79,121.67 52.2,121.26 ; v3(51.44,85.47) 50.15,85.47 49.77,85.85 49.77,85.87 U1.PAD ; v1(56.9,113.64) 56.9,113.13 C90.2 ; R44.2 v3(38.99,87.63) ; C114.N v3(54.23,37.47) ; C120.2 56.9,49.89 56.9,49.63 v1(57.28,49.25) ; v3(51.94,118.34) 52.07,118.47 C137.2 ; C126.2 56.9,51.54 v1(56.9,52.04) ; C142.2 56.9,119.48 v1(56.9,119.1) C89.2 ; C84.2 56.9,57.89 v1(56.9,57.51) C128.2 ; 52.2,59.66 v2(51.56,60.3) ; R9.2 v3(34.92,78.99) ; C54.2 45.59,50.33 v3(45.59,50.77) ; C116.N v1(52.32,41.63) ; R12.1 v3(37.85,90.42) ; v3(45.59,112.37) 45.59,111.92 C117.2 ; v3(78.11,72.64) v3(75.06,72.64) ; C122.2 45.97,120.75 v3(45.97,119.99) ; R23.2 v3(38.99,86.49) ; C106.2 v3(45.09,113.26) ; C127.2 v3(56.9,54.86) ; R42.2 v3(58.8,88.01) ; R7.2 v3(58.8,85.98) ; C60.2 52.07,56.87 v3(51.94,56.74) ; R32.2 v3(38.86,83.19) ; R3.2 v1(59.63,62.9) ; v3(81.79,96.77) T7.3 ; T7.3 v3(83.69,98.17) ; T7.3 v3(79.88,98.17) ; R28.2 v3(58.8,84.84) ; v3(45.97,58.39) 45.97,59.16 C69.2 ; T2.4 v3(59.44,101.35) ; C83.2 46.74,56.87 v3(46.61,56.74) ; C87.2 v3(56.9,116.33) ; C66.2 v1(20.7,90.17) ; C76.2 v3(45.09,58.14) ; v3(48.13,118.34) C149.2 ; R11.1 v3(37.59,89.03) ; C25.2 v1(20.7,92.2) ; C123.2 v3(45.09,119.74) ; C118.2 v1(60.07,44.04) ; C70.2 v1(21.59,82.04) ; v3(81.66,76.58) T3.1 v3(80.26,75.18) ; R21.2 v1(59.63,124.5)
  vias: v1(2.54,127.13) v1(2.54,38.86) v1(3.05,129.16) v1(3.05,48.13) v1(3.17,54.99) v1(3.68,117.35) v1(4.7,159.64) v1(4.83,133.73) v1(4.95,37.97) v1(5.21,23.37) v1(5.33,123.7) v1(5.59,52.7) v1(6.22,140.72) v1(6.35,129.03) v1(6.48,166.37) v1(6.86,154.81) v1(6.86,36.96) v1(7.87,51.56) v1(8.26,36.32) v1(8.64,175.89) v1(8.64,132.72) v1(8.89,18.03) v1(9.52,148.72) v1(9.65,160.78) v1(9.78,123.32) v1(9.91,41.4) v1(10.03,57.02) v1(10.41,29.84) v1(10.67,119.63) v1(11.05,133.86) v1(11.43,34.92) v1(11.43,10.67) v1(12.19,42.93) v1(12.32,38.23) v1(12.83,24.77) v1(13.72,35.31) v1(13.97,132.84) v1(14.61,44.45) v1(15.11,98.55) v1(15.37,35.56) v1(15.88,15.62) v1(16.13,79.63) v1(16.13,64.9) v1(16.26,8.64) v1(16.38,95.76) v1(16.51,42.55) v1(16.64,136.53) v1(17.27,75.31) v1(17.27,22.23) v1(17.65,35.81) v1(18.03,145.16) v1(18.29,149.35) v1(18.92,136.53) v1(19.69,36.07) v1(20.57,135.13) v1(21.08,42.8) v1(22.23,35.94) v1(23.5,136.02) v1(23.88,22.73) v1(24,14.73) v1(24.38,44.58) v1(24.51,30.1) v1(24.64,36.83) v1(24.77,111.89) v1(24.77,103.63) v1(25.27,135.13) v1(25.27,39.12) v1(25.65,139.83) v1(26.42,156.08) v1(27.18,18.8) v1(27.43,146.69) v1(27.43,39.24) v1(27.69,135.25) v1(27.69,15.62) v1(28.7,176.4) v1(29.34,152.27) v1(29.46,39.75) v1(29.85,134.11) v1(29.97,103.25) v1(30.73,136.53) v1(30.73,54.1) v1(30.73,40.89) v1(31.12,37.59) v1(31.24,48.13) v1(31.37,21.21) v1(31.75,132.08) v1(31.75,71.37) v1(31.88,61.21) v1(33.15,130.81) v1(33.27,141.22) v1(33.4,41.15) v1(33.4,38.73) v1(33.91,59.94) v1(34.29,116.59) v1(34.8,92.08) v1(35.43,111) v1(35.69,81.41) v1(35.94,34.92) v1(36.2,136.14) v1(36.45,21.97) v1(36.45,11.43) v1(36.83,130.05) v1(37.21,108.94) v1(37.34,145.92) v1(37.47,27.3) v1(37.47,24.26) v1(38.1,49.53) v1(38.48,121.92) v1(38.48,35.05) v1(38.99,60.33) v1(39.24,40.26) v1(39.24,29.34) v1(40.01,108.69) v1(40.13,128.52) v1(40.77,150.62) v1(40.89,79.12) v1(41.91,142.24) v1(43.31,75.56) v1(44.07,11.05) v1(44.32,136.14) v1(44.32,36.07) v1(44.32,3.56) v1(45.09,131.57) v1(45.21,176.78) v1(45.59,70.23) v1(45.97,147.83) v1(46.36,163.83) v1(47.37,71.75) v1(47.5,78.49) v1(47.75,70.1) v1(48.9,106.05) v1(49.15,143.13) v1(49.15,2.92) v1(50.67,73.79) v1(51.44,130.05) v1(52.7,68.71) v1(52.7,36.83) v1(53.21,6.86) v1(53.47,151.13) v1(53.72,79.5) v1(53.85,138.81) v1(54.23,43.79) v1(54.23,12.7) v1(54.23,4.32) v1(54.48,68.83) v1(55.37,45.72) v1(55.5,43.92) v1(56.13,65.02) v1(56.9,120.75) v1(56.9,59.16) v1(57.4,146.05) v1(57.66,128.91) v1(59.18,70.23) v1(60.2,12.95) v1(60.33,122.28) v1(60.33,50.55) v1(60.33,41.53) v1(60.45,133.35) v1(60.71,113.66) v1(60.96,37.08) v1(62.87,151.38) v1(62.87,125.7) v1(62.87,122.53) v1(63.25,27.43) v1(63.5,15.11) v1(63.88,176.4) v1(63.88,159.38) v1(64.26,129.54) v1(64.26,9.02) v1(65.15,93.98) v1(65.53,141.22) v1(65.53,99.82) v1(65.53,97.92) v1(65.53,96.27) v1(65.53,95) v1(65.53,87.88) v1(65.53,86.23) v1(65.53,74.3) v1(65.53,50.93) v1(65.66,79.12) v1(65.66,77.47) v1(65.66,76.07) v1(65.66,72.77) v1(66.42,101.6) v1(66.67,25.65) v1(67.06,71.5) v1(67.18,118.11) v1(67.31,41.27) v1(67.44,104.39) v1(67.69,156.59) v1(68.2,102.36) v1(68.2,78.11) v1(68.2,76.33) v1(68.2,74.68) v1(68.33,98.93) v1(68.33,96.9) v1(68.33,95.38) v1(68.71,175.64) v1(68.71,86.74) v1(68.96,30.35) v1(69.47,144.14) v1(69.85,137.03) v1(69.98,57.28) v1(70.23,93.98) v1(70.23,79.63) v1(70.23,67.94) v1(70.48,149.22) v1(70.74,86.74) v1(71.37,121.92) v1(71.37,34.42) v1(71.75,26.8) v1(72.77,138.43) v1(73.15,86.74) v1(74.04,93.98) v1(74.04,79.63) v1(74.93,128.91) v1(75.06,86.74) v1(75.31,42.93) v1(75.56,50.04) v1(76.71,55.24) v1(77.22,145.42) v1(77.22,34.67) v1(77.6,6.6) v1(77.98,135.76) v1(78.36,91.82) v1(78.36,89.92) v1(78.36,83.69) v1(78.36,81.28) v1(78.36,26.16) v1(78.87,107.7) v1(80.01,80.9) v1(80.14,89.92) v1(80.26,93.47) v1(80.26,83.44) v1(80.52,30.1) v1(80.64,87) v1(81.28,115.82) v1(81.28,79.76) v1(81.53,91.31) v1(81.79,94.61) v1(81.91,82.17) v1(82.3,78.61) v1(82.68,112.01) v1(82.93,95.76) v1(82.93,92.84) v1(83.44,43.94) v1(83.95,136.91) v1(84.07,93.98) v1(84.2,96.9) v1(84.33,84.07) v1(84.33,82.68) v1(84.33,81.28) v1(84.45,72.9) v1(84.71,49.91) v1(84.85,79.9) v1(85.09,94.36) v1(85.22,76.96) v1(85.6,35.56) v1(85.6,29.46) v1(85.72,96.9) v1(85.85,72.77) v1(85.98,75.06) v1(86.11,79.5) v1(86.87,26.29) v1(87,76.96) v1(87.07,38.94) v1(87.12,96.9) v1(87.38,161.16) v1(87.38,79.5) v1(87.38,75.06) v1(87.38,72.77) v1(87.5,133.6) v1(87.76,7.49) v1(88.52,96.9) v1(88.52,76.96) v1(88.65,79.5) v1(88.77,80.64) v1(88.77,75.06) v1(88.77,72.77) v1(89.28,67.44) v1(89.53,119.13) v1(89.66,176.02) v1(89.66,151.76) v1(90.04,96.9) v1(90.04,76.96) v1(90.17,56.52) v1(90.3,75.06) v1(90.3,72.77) v1(90.68,139.06) v1(90.93,77.98) v1(91.06,96.14) v1(91.19,80.64) v1(91.19,79.5) v1(91.31,166.62) v1(91.31,93.85) v1(91.31,16.26) v1(91.44,94.87) v1(91.44,92.58) v1(91.57,157.1) v1(91.95,75.06) v1(91.95,72.77) v1(91.95,36.58) v1(91.95,22.35) v1(93.09,45.85) v1(93.09,41.78) v1(93.22,30.23) v1(93.47,78.44) v1(93.6,75.06) v1(93.6,72.77) v1(94.49,136.14) v1(94.49,98.81) v1(94.49,17.91) v1(94.74,87.88) v1(94.74,86.23) v1(94.74,84.45) v1(95.12,90.55) v1(95.12,25.65) v1(95.5,75.06) v1(95.5,72.77) v1(95.5,12.95) v1(95.76,39.62) v1(96.27,149.48) v1(96.27,114.43) v1(96.39,138.3) v1(96.65,88.39) v1(96.65,85.72) v1(96.65,29.72) v1(97.03,72.77) v1(97.03,23.49) v1(97.16,75.06) v1(98.04,88.39) v1(98.04,85.72) v1(98.55,61.72) v1(98.81,75.06) v1(98.81,72.77) v1(99.31,106.17) v1(99.31,87.76) v1(99.31,86.11) v1(99.31,50.67) v1(100.46,75.06) v1(100.46,72.77) v1(100.46,36.58) v1(100.46,19.43) v1(100.84,87.76) v1(100.84,86.11) v1(100.97,96.65) v1(100.97,71.56) v1(101.47,30.86) v1(102.11,100.71) v1(102.23,25.27) v1(102.49,76.96) v1(102.62,119.63) v1(102.62,70.74) v1(102.87,45.21) v1(103.12,162.69) v1(103.76,173.1) v1(103.76,112.01) v1(103.76,76.96) v1(103.76,14.48) v1(103.89,70.74) v1(104.01,61.34) v1(105.03,76.96) v1(105.03,70.74) v1(106.17,76.96) v1(106.3,70.74) v2(2.03,41.91) v2(2.54,43.81) v2(3.81,124.97) v2(3.94,38.35) v2(4.45,40.77) v2(4.57,43.05) v2(6.22,40) v2(8,39.37) v2(8.13,127.25) v2(9.4,130.3) v2(9.91,39.5) v2(9.91,37.08) v2(10.03,43.43) v2(11.68,131.57) v2(14.22,131.06) v2(14.61,38.1) v2(16.13,134.37) v2(16.64,38.35) v2(18.16,134.37) v2(18.54,38.35) v2(20.57,132.84) v2(21.08,38.23) v2(22.86,133.48) v2(22.86,38.61) v2(24.38,41.27) v2(24.51,132.59) v2(24.51,50.93) v2(26.42,132.84) v2(28.19,41.91) v2(28.45,39.5) v2(28.57,132.21) v2(29.97,130.56) v2(30.1,14.22) v2(30.23,50.04) v2(31.24,23.88) v2(31.75,67.18) v2(33.02,129.29) v2(34.04,79.63) v2(34.29,54.61) v2(34.92,67.18) v2(35.56,127.89) v2(35.69,24.38) v2(40.13,126.87) v2(40.77,26.03) v2(42.29,68.2) v2(45.85,68.2) v2(45.85,66.67) v2(49.78,128.27) v2(51.44,66.67) v2(55.25,66.04) v2(56.26,67.82) v2(58.55,65.15) v2(61.85,34.04) v2(63.75,30.99) v2(65.28,38.1) v2(65.66,65.91) v2(66.17,55.12) v3(41.3,17.53) v3(45.34,117.2) v3(45.34,55.6) v3(46.61,116.18) v3(46.61,114.91) v3(46.61,113.77) v3(46.61,54.58) v3(46.61,53.31) v3(46.61,52.17) v3(46.65,117.31) v3(46.65,55.71) v3(48.01,113.77) v3(48.01,52.17) v3(48.14,117.31) v3(48.13,116.18) v3(48.13,114.91) v3(48.14,55.71) v3(48.13,54.58) v3(48.13,53.31) v3(49.15,113.77) v3(49.15,52.17) v3(49.28,117.31) v3(49.28,116.18) v3(49.28,114.91) v3(49.28,55.71) v3(49.28,54.58) v3(49.28,53.31) v3(49.66,118.34) v3(49.66,56.74) v3(50.16,107.8) v3(50.29,113.77) v3(50.29,52.17) v3(50.55,115.93) v3(50.55,54.33) v3(50.67,118.34) v3(50.67,56.74) v3(51.05,117.31) v3(51.05,55.71) v3(51.31,116.05) v3(51.31,114.91) v3(51.31,113.77) v3(51.31,54.46) v3(51.31,53.31) v3(51.31,52.17) v3(89.41,87.38) v3(89.41,86.23) v3(90.68,87.38) v3(90.68,86.23) v4(102.73,88.06) v4(102.73,85.93) v4(102.73,75.11) v4(102.73,72.97) v4(104,88.06) v4(104,85.93) v4(104,75.11) v4(104,72.97) v4(105.27,88.06) v4(105.27,85.93) v4(105.27,75.11) v4(105.27,72.97) v4(106.54,88.06) v4(106.54,85.93) v4(106.54,75.11) v4(106.54,72.97)
CVDD18: length 37.5
  TOP w0.203: v3(54.74,120.75) 54.29,120.31 X1.72 ; v3(54.1,59.66) 53.74,59.3 X2.1 ; v3(51.6,58.14) 51.6,58.23 51.65,58.27 X2.4 ; X2.71 52.9,58.21 v3(52.83,58.14) ; X1.1 53.74,120.89 v3(54.1,121.26) ; v3(52.83,119.74) 52.9,119.81 X1.71 ; v3(51.6,119.74) 51.6,119.82 51.65,119.87 X1.4 ; X2.72 54.29,58.71 v3(54.74,59.16)
  TOP w0.254: X1.64 53.09,116.31 v3(52.83,116.05) 53.08,115.81 X1.63 ; X1.60 53.21,114.31 52.82,113.92 52.82,113.82 v3(52.81,113.81) X1.59 ; X2.64 53.09,54.71 v3(52.83,54.46) 53.08,54.21 X2.63 ; X2.60 53.21,52.71 52.82,52.32 52.82,52.22 v3(52.81,52.21) X2.59
  TOP w0.381: 51.26,156.97 TP1.1 ; TP1.1 53.65,156.97 ; TP1.1 52.45,158.17 ; TP1.1 52.45,155.78
  TOP w0.508: v1(55.37,97.92) C147.P v1(56.9,99.44) ; E1.2 52.45,161.1 v1(52.45,160.78)
  L6_PWR w0.254: TP1.1 52.45,158.17 ; TP1.1 52.45,155.78 ; TP1.1 53.65,156.97 ; TP1.1 51.26,156.97
  BOTTOM w0.508: C142.1 C140.1 v3(54.74,120.75) ; C144.1 v3(54.1,121.26) ; C137.1 v3(52.83,119.74) ; 52.7,52.17 52.74,52.21 v3(52.81,52.21) ; 52.7,113.77 52.74,113.81 v3(52.81,113.81) ; C60.1 v3(52.83,58.14) ; C84.1 C78.1 v3(54.74,59.16) ; C88.1 v3(54.1,59.66) ; C139.1 v3(51.6,119.74) ; C71.1 v3(51.6,58.14)
  vias: v1(50.93,160.78) v1(50.93,159.64) v1(52.45,159.64) v1(53.98,160.78) v1(53.98,159.64) v3(52.83,114.91) v3(52.83,53.31)
D0_N: length 102.7
  TOP w0.127: v2(3.43,125.67) 3.75,125.98 13.97,125.98 18.54,121.41 18.54,120.9 26.92,112.52 26.92,108.46 30.99,104.39 42.52,104.39 43.03,104.9 44.83,104.9 49.52,109.59 49.52,110.62 49.65,110.74 X1.47
  L3_SIGNAL w0.127: v2(3.43,125.67) 3.11,125.98 2.67,125.98 2.41,125.73 2.41,122.81 3.3,121.92 11.41,121.92 13.84,119.49 13.84,107.82 12.94,106.92 3.01,106.92 2.88,106.79 2.88,106.67 P2.B8
D0_P: length 102.7
  TOP w0.127: v2(3.43,126.56) 3.75,126.24 14.08,126.24 18.8,121.52 18.8,121.01 27.18,112.63 27.18,108.56 31.09,104.65 42.42,104.65 42.93,105.16 44.73,105.16 49.27,109.7 49.27,110.62 49.14,110.74 X1.46
  L3_SIGNAL w0.127: v2(3.43,126.56) 3.11,126.24 2.56,126.24 2.16,125.84 2.16,122.7 3.2,121.67 11.3,121.67 13.59,119.38 13.59,107.93 12.84,107.18 2.91,107.18 2.63,106.9 2.63,106.67 P2.A8
D1_N: length 102.7
  TOP w0.127: v2(7.37,127.7) 7.68,128.02 13.72,128.02 27.69,114.05 27.69,109.75 32.03,105.41 42.16,105.41 42.67,105.92 44.7,105.92 48.52,109.74 48.52,110.62 48.65,110.74 X1.45
  L3_SIGNAL w0.127: P2.B7 2.88,104.17 2.88,104.29 3.01,104.42 14.38,104.42 14.86,104.9 14.86,120.78 10.41,125.22 5.46,125.22 4.57,126.11 4.57,127.64 4.95,128.02 7.05,128.02 v2(7.37,127.7)
D1_P: length 102.7
  TOP w0.127: v2(7.37,128.59) 7.68,128.27 13.82,128.27 27.94,114.15 27.94,109.85 32.13,105.66 42.06,105.66 42.57,106.17 44.6,106.17 48.27,109.84 48.27,110.62 48.14,110.74 X1.44
  L3_SIGNAL w0.127: v2(7.37,128.59) 7.05,128.27 4.85,128.27 4.32,127.74 4.32,126.01 5.36,124.97 10.31,124.97 14.61,120.67 14.61,105.01 14.27,104.68 2.91,104.68 2.63,104.4 2.63,104.17 P2.A7
D2_0_N: length 103
  TOP w0.127: v2(33.66,42.24) 33.96,42.55 42.29,42.55 43.43,43.69 45.21,43.69 49.52,48 49.52,49.03 49.65,49.15 X2.47
  L8_SIGNAL w0.127: P2.D8 7.38,106.67 7.38,106.79 7.65,107.06 16.91,107.06 29.21,94.76 29.21,45.47 32.13,42.55 33.35,42.55 v2(33.66,42.24)
D2_0_P: length 103
  TOP w0.127: v2(33.66,43.1) 33.83,42.93 33.84,42.93 33.97,42.8 42.16,42.8 43.31,43.94 45.11,43.94 49.27,48.1 49.27,49.03 49.14,49.15 X2.46
  L8_SIGNAL w0.127: v2(33.66,43.1) 33.35,42.8 32.24,42.8 29.46,45.57 29.46,94.87 17.02,107.31 7.54,107.31 7.13,106.9 7.13,106.67 P2.C8
D2_1_N: length 102.7
  TOP w0.127: X2.45 48.65,49.15 48.52,49.03 48.52,48.14 44.7,44.32 42.67,44.32 41.91,43.56 35.05,43.56 34.16,44.45 33.4,44.45 31.24,42.29 30.78,42.29 v2(30.48,41.99)
  L8_SIGNAL w0.127: v2(30.48,41.99) 30.18,42.29 28.98,42.29 28.07,43.2 28.07,93.98 17.53,104.52 7.61,104.52 7.38,104.29 7.38,104.17 P2.D7
D2_1_P: length 102.7
  TOP w0.127: v2(30.48,42.85) 30.78,42.55 31.14,42.55 33.3,44.7 34.27,44.7 35.16,43.81 41.8,43.81 42.57,44.58 44.6,44.58 48.27,48.25 48.27,49.03 48.14,49.15 X2.44
  L8_SIGNAL w0.127: v2(30.48,42.85) 30.18,42.55 29.08,42.55 28.32,43.31 28.32,94.09 17.63,104.78 7.5,104.78 7.13,104.4 7.13,104.17 P2.C7
D2_2_N: length 103.1
  TOP w0.127: X2.42 47.14,49.15 47.02,49.03 47.02,47.91 44.2,45.09 42.42,45.09 41.91,44.58 35.69,44.58 34.67,45.59 32.39,45.59 30.86,44.07 29.82,44.07 29.34,43.58 29.34,41.53 29.01,41.2 29.01,40.79 28.73,40.52 28.5,40.52 v2(28.2,40.22)
  L8_SIGNAL w0.127: P2.D6 7.38,101.67 7.38,101.79 7.7,102.11 16.28,102.11 27.05,91.33 27.05,41.13 27.67,40.52 27.9,40.52 v2(28.2,40.22)
D2_2_P: length 103.1
  TOP w0.127: v2(28.2,41.07) 28.5,40.77 28.63,40.77 28.75,40.9 28.75,41.31 29.08,41.63 29.08,43.69 29.72,44.32 30.76,44.32 32.28,45.85 34.78,45.85 35.79,44.83 41.8,44.83 42.31,45.34 44.09,45.34 46.77,48.02 46.77,49.03 46.65,49.15 X2.41
  L8_SIGNAL w0.127: P2.C6 7.13,101.67 7.13,101.9 7.59,102.36 16.38,102.36 27.3,91.44 27.3,41.24 27.77,40.77 27.9,40.77 v2(28.2,41.07)
D2_3_N: length 102.8
  TOP w0.127: X2.40 46.14,49.15 46.02,49.03 46.02,47.93 43.94,45.85 41.91,45.85 41.4,45.34 36.45,45.34 33.91,47.88 32.64,47.88 29.72,44.96 28.68,44.96 27.43,43.71 27.43,40.53 27.16,40.26 26.84,40.26 v2(26.54,39.96)
  L8_SIGNAL w0.127: v2(26.54,39.96) 26.24,40.26 26.01,40.26 25.73,40.53 25.73,41.18 25.95,41.39 25.95,90.03 16.4,99.57 7.66,99.57 7.38,99.29 7.38,99.17 P2.D5
D2_3_P: length 102.8
  TOP w0.127: X2.39 45.65,49.15 45.77,49.03 45.77,48.03 43.84,46.1 41.8,46.1 41.3,45.59 36.55,45.59 34.01,48.13 32.53,48.13 29.61,45.21 28.57,45.21 27.18,43.81 27.18,40.64 27.05,40.51 26.84,40.51 v2(26.54,40.81)
  L8_SIGNAL w0.127: v2(26.54,40.81) 26.24,40.51 26.12,40.51 25.99,40.64 25.99,41.07 26.2,41.28 26.2,90.13 16.51,99.82 7.55,99.82 7.13,99.4 7.13,99.17 P2.C5
D2_4_N: length 102.9
  TOP w0.127: v2(24.26,39.58) 25.27,40.59 25.27,43.33 27.94,46 27.94,46.5 31.09,49.66 34.67,49.66 37.72,46.61 43.56,46.61 45.02,48.07 45.02,49.03 45.14,49.15 X2.38
  L8_SIGNAL w0.127: v2(24.26,39.58) 23.96,39.88 23.72,39.88 23.45,40.15 23.45,40.83 23.62,41.01 23.62,42.9 25.02,44.3 25.02,88.9 16.89,97.03 7.62,97.03 7.38,96.79 7.38,96.67 P2.D4
D2_4_P: length 102.8
  TOP w0.127: v2(24.26,40.43) 24.5,40.18 25.02,40.7 25.02,43.43 27.69,46.1 27.69,46.61 30.99,49.91 34.78,49.91 37.82,46.86 43.46,46.86 44.77,48.18 44.77,49.03 44.65,49.15 X2.37
  L8_SIGNAL w0.127: v2(24.26,40.43) 23.96,40.13 23.83,40.13 23.7,40.26 23.7,40.73 23.88,40.9 23.88,42.8 25.27,44.2 25.27,89.01 17,97.28 7.51,97.28 7.13,96.9 7.13,96.67 P2.C4
D2_5_N: length 102.6
  TOP w0.127: X2.35 43.58,50.71 43.46,50.83 29.24,50.83 23.62,45.21 23.62,39.09 24.29,38.43 24.29,37.76 24.01,37.48 23.78,37.48 v2(23.48,37.18)
  L8_SIGNAL w0.127: v2(23.48,37.18) 23.18,37.48 22.82,37.48 22.49,37.81 22.49,37.86 22.1,38.25 22.1,43.79 23.75,45.44 23.75,85.47 14.61,94.61 7.7,94.61 7.38,94.29 7.38,94.17 P2.D3
D2_5_P: length 103.1
  TOP w0.127: X2.34 43.58,51.21 43.46,51.09 29.14,51.09 23.37,45.32 23.37,38.99 24.03,38.32 24.03,37.86 23.91,37.74 23.78,37.74 v2(23.48,38.04)
  L8_SIGNAL w0.127: v2(23.48,38.04) 23.18,37.74 22.92,37.74 22.74,37.92 22.74,37.96 22.35,38.35 22.35,43.69 24,45.34 24,85.58 14.71,94.87 7.6,94.87 7.13,94.4 7.13,94.17 P2.C3
D2_6_N: length 102.7
  TOP w0.127: X2.33 43.58,51.71 43.46,51.83 28.57,51.83 22.23,45.49 22.23,37.49 21.66,36.92 21.42,36.92 v2(21.12,36.62)
  L8_SIGNAL w0.127: P2.D2 7.38,91.67 7.38,91.79 7.79,92.2 14.61,92.2 22.35,84.45 22.35,46.21 20.07,43.92 20.07,37.99 20.31,37.75 20.31,37.19 20.59,36.92 20.82,36.92 v2(21.12,36.62)
D2_6_P: length 103.1
  TOP w0.127: v2(21.12,37.47) 21.42,37.17 21.55,37.17 21.97,37.59 21.97,45.59 28.47,52.09 43.46,52.09 43.58,52.21 X2.32
  L8_SIGNAL w0.127: v2(21.12,37.47) 20.82,37.17 20.69,37.17 20.57,37.3 20.57,37.85 20.32,38.1 20.32,43.81 22.61,46.1 22.61,84.56 14.71,92.46 7.69,92.46 7.13,91.9 7.13,91.67 P2.C2
D2_7_N: length 102.6
  TOP w0.127: v2(18.92,36.91) 19.22,37.21 19.46,37.21 19.73,37.49 19.73,37.98 19.43,38.28 19.43,43.96 28.3,52.83 43.46,52.83 43.58,52.71 X2.31
  L8_SIGNAL w0.127: P2.D1 7.38,89.17 7.38,89.29 7.75,89.66 14.86,89.66 19.94,84.58 19.94,81.53 21.21,80.26 21.21,47.5 17.4,43.69 17.4,37.72 17.91,37.21 18.62,37.21 v2(18.92,36.91)
D2_7_P: length 103.1
  TOP w0.127: v2(18.92,37.77) 19.22,37.47 19.35,37.47 19.48,37.59 19.48,37.88 19.18,38.18 19.18,44.07 28.2,53.09 43.46,53.09 43.58,53.21 X2.30
  L8_SIGNAL w0.127: v2(18.92,37.77) 18.62,37.47 18.01,37.47 17.65,37.82 17.65,43.58 21.46,47.39 21.46,80.37 20.19,81.64 20.19,84.69 14.96,89.92 7.65,89.92 7.13,89.4 7.13,89.17 P2.C1
D2_8_N: length 102.7
  TOP w0.127: v2(16.64,36.66) 16.94,36.96 17.25,36.96 17.78,37.49 17.78,45.97 26.92,55.12 35.43,55.12 35.72,54.83 43.46,54.83 43.58,54.71 X2.27
  L8_SIGNAL w0.127: v2(16.64,36.66) 16.34,36.96 15.98,36.96 15.75,37.19 15.75,37.61 15.24,38.12 15.24,43.05 20.07,47.88 20.07,79.12 14.73,84.45 14.73,85.09 13.59,86.23 7.86,86.23 7.38,85.76 7.38,85.63 P1.D10
D2_8_P: length 103.1
  TOP w0.127: v2(16.64,37.51) 16.94,37.21 17.14,37.21 17.53,37.59 17.53,46.08 26.82,55.37 35.54,55.37 35.82,55.09 43.46,55.09 43.58,55.21 X2.26
  L8_SIGNAL w0.127: P1.C10 7.13,85.63 7.13,85.86 7.75,86.49 13.69,86.49 14.99,85.2 14.99,84.56 20.32,79.23 20.32,47.77 15.49,42.95 15.49,38.23 16,37.72 16,37.29 16.08,37.21 16.34,37.21 v2(16.64,37.51)
D2_9_N: length 102.7
  TOP w0.127: v2(14.99,36.53) 15.29,36.83 15.52,36.83 15.79,37.11 15.79,37.72 15.56,37.96 15.56,46.06 25.33,55.83 43.46,55.83 43.58,55.71 X2.25
  L8_SIGNAL w0.127: v2(14.99,36.53) 14.69,36.83 13.97,36.83 13.72,37.08 13.72,45.57 19.05,50.91 19.05,78.23 13.59,83.69 7.82,83.69 7.38,83.26 7.38,83.13 P1.D9
D2_9_P: length 103.1
  TOP w0.127: v2(14.99,37.38) 15.29,37.08 15.41,37.08 15.54,37.21 15.54,37.62 15.3,37.85 15.3,46.16 25.23,56.09 43.46,56.09 43.58,56.21 X2.24
  L8_SIGNAL w0.127: v2(14.99,37.38) 14.69,37.08 14.08,37.08 13.97,37.19 13.97,45.47 19.3,50.8 19.3,78.34 13.69,83.95 7.71,83.95 7.13,83.36 7.13,83.13 P1.C9
